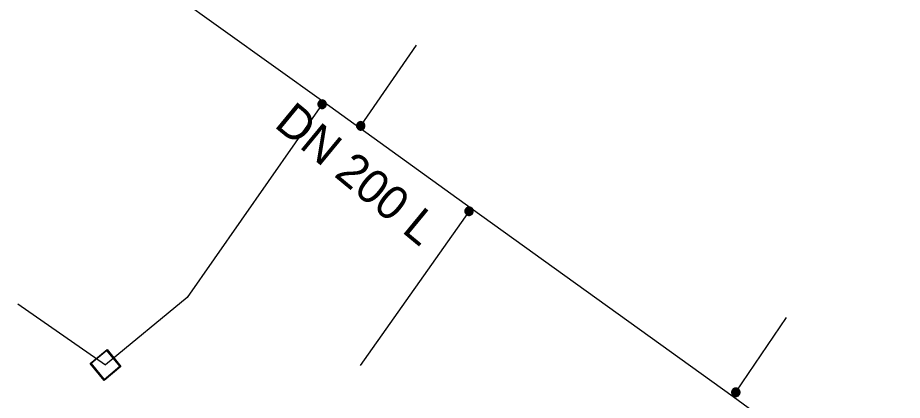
# Model space of a CAD drawing. Extents: x -832382 to -831581, y -1074670 to -1074251.
# Drawn here: x -831679.3 to -831626.9, y -1074502.9 to -1074480.2 of the extents above; entities that cross this region are included whole.
import ezdxf

# ---------------------------------------------------------------- set-up
doc = ezdxf.new("R2010")
doc.units = 0
for name, color, linetype in [('Přípojka vodovodu', 7, 'Continuous'), ('Přípojkový uzávěr', 7, 'Continuous'), ('Roz-řad', 7, 'Continuous'), ('Roz-řad-popis základní', 7, 'Continuous'), ('Šachta vodovodní', 7, 'Continuous')]:
    doc.layers.add(name, color=color, linetype=linetype)

msp = doc.modelspace()

# ---------------------------------------------------------------- linework, layer by layer
at = {"layer": 'Přípojka vodovodu'}
msp.add_line((-831679.298, -1074497.2), (-831674.092, -1074500.816), dxfattribs=at)
for points in [[(-831659.022, -1074486.757), (-831658.96, -1074486.64), (-831655.662, -1074481.85)], [(-831661.155, -1074485.222), (-831661.249, -1074485.356), (-831669.245, -1074496.822), (-831674.092, -1074500.816)], [(-831652.411, -1074491.516), (-831652.538, -1074491.697), (-831658.987, -1074500.857)], [(-831636.886, -1074502.691), (-831636.72, -1074502.44), (-831633.711, -1074498.013)]]:
    msp.add_lwpolyline(points, dxfattribs=at)
at = {"layer": 'Přípojkový uzávěr'}
for points in [[(-831661.249, -1074485.106), (-831661.186, -1074485.106), (-831661.126, -1074485.138), (-831661.066, -1074485.171), (-831661.032, -1074485.231), (-831660.999, -1074485.291), (-831660.999, -1074485.356), (-831660.999, -1074485.421), (-831661.032, -1074485.481), (-831661.065, -1074485.54), (-831661.124, -1074485.573), (-831661.184, -1074485.606), (-831661.249, -1074485.606), (-831661.314, -1074485.606), (-831661.373, -1074485.573), (-831661.433, -1074485.54), (-831661.466, -1074485.481), (-831661.499, -1074485.421), (-831661.499, -1074485.356), (-831661.499, -1074485.291), (-831661.465, -1074485.231), (-831661.432, -1074485.171), (-831661.372, -1074485.138), (-831661.312, -1074485.106), (-831661.249, -1074485.106)], [(-831661.249, -1074485.129), (-831661.306, -1074485.129), (-831661.36, -1074485.159), (-831661.414, -1074485.188), (-831661.445, -1074485.242), (-831661.475, -1074485.297), (-831661.475, -1074485.356), (-831661.475, -1074485.415), (-831661.445, -1074485.469), (-831661.416, -1074485.523), (-831661.362, -1074485.553), (-831661.307, -1074485.583), (-831661.249, -1074485.583), (-831661.19, -1074485.583), (-831661.136, -1074485.553), (-831661.082, -1074485.523), (-831661.052, -1074485.469), (-831661.022, -1074485.415), (-831661.022, -1074485.356), (-831661.022, -1074485.297), (-831661.053, -1074485.242), (-831661.084, -1074485.188), (-831661.138, -1074485.159), (-831661.192, -1074485.129), (-831661.249, -1074485.129)], [(-831661.249, -1074485.147), (-831661.196, -1074485.147), (-831661.146, -1074485.174), (-831661.096, -1074485.201), (-831661.068, -1074485.251), (-831661.039, -1074485.301), (-831661.039, -1074485.356), (-831661.039, -1074485.411), (-831661.067, -1074485.461), (-831661.094, -1074485.51), (-831661.144, -1074485.538), (-831661.194, -1074485.566), (-831661.249, -1074485.566), (-831661.303, -1074485.566), (-831661.353, -1074485.538), (-831661.403, -1074485.51), (-831661.431, -1074485.461), (-831661.458, -1074485.411), (-831661.458, -1074485.356), (-831661.458, -1074485.301), (-831661.43, -1074485.251), (-831661.402, -1074485.201), (-831661.352, -1074485.174), (-831661.302, -1074485.147), (-831661.249, -1074485.147)], [(-831661.249, -1074485.169), (-831661.327, -1074485.169), (-831661.382, -1074485.223), (-831661.436, -1074485.278), (-831661.436, -1074485.356), (-831661.436, -1074485.434), (-831661.381, -1074485.489), (-831661.326, -1074485.544), (-831661.249, -1074485.544), (-831661.171, -1074485.544), (-831661.116, -1074485.489), (-831661.061, -1074485.434), (-831661.061, -1074485.356), (-831661.061, -1074485.278), (-831661.116, -1074485.223), (-831661.17, -1074485.169), (-831661.249, -1074485.169)], [(-831661.249, -1074485.191), (-831661.181, -1074485.191), (-831661.133, -1074485.239), (-831661.085, -1074485.287), (-831661.085, -1074485.356), (-831661.085, -1074485.424), (-831661.133, -1074485.472), (-831661.181, -1074485.52), (-831661.249, -1074485.52), (-831661.317, -1074485.52), (-831661.365, -1074485.472), (-831661.413, -1074485.424), (-831661.413, -1074485.356), (-831661.413, -1074485.287), (-831661.365, -1074485.239), (-831661.317, -1074485.191), (-831661.249, -1074485.191)], [(-831661.249, -1074485.211), (-831661.309, -1074485.211), (-831661.351, -1074485.254), (-831661.393, -1074485.296), (-831661.393, -1074485.356), (-831661.393, -1074485.415), (-831661.351, -1074485.458), (-831661.309, -1074485.5), (-831661.249, -1074485.5), (-831661.189, -1074485.5), (-831661.147, -1074485.458), (-831661.105, -1074485.415), (-831661.105, -1074485.356), (-831661.105, -1074485.296), (-831661.147, -1074485.254), (-831661.189, -1074485.211), (-831661.249, -1074485.211)], [(-831661.249, -1074485.231), (-831661.196, -1074485.231), (-831661.16, -1074485.268), (-831661.124, -1074485.304), (-831661.124, -1074485.356), (-831661.124, -1074485.408), (-831661.16, -1074485.445), (-831661.197, -1074485.481), (-831661.249, -1074485.481), (-831661.3, -1074485.481), (-831661.337, -1074485.445), (-831661.374, -1074485.408), (-831661.374, -1074485.356), (-831661.374, -1074485.304), (-831661.337, -1074485.268), (-831661.301, -1074485.231), (-831661.249, -1074485.231)], [(-831661.249, -1074485.254), (-831661.291, -1074485.254), (-831661.321, -1074485.284), (-831661.35, -1074485.314), (-831661.35, -1074485.356), (-831661.35, -1074485.398), (-831661.321, -1074485.428), (-831661.291, -1074485.457), (-831661.249, -1074485.457), (-831661.207, -1074485.457), (-831661.177, -1074485.428), (-831661.147, -1074485.398), (-831661.147, -1074485.356), (-831661.147, -1074485.314), (-831661.177, -1074485.284), (-831661.207, -1074485.254), (-831661.249, -1074485.254)], [(-831661.249, -1074485.272), (-831661.214, -1074485.272), (-831661.189, -1074485.296), (-831661.165, -1074485.321), (-831661.165, -1074485.356), (-831661.165, -1074485.391), (-831661.189, -1074485.415), (-831661.214, -1074485.44), (-831661.249, -1074485.44), (-831661.284, -1074485.44), (-831661.309, -1074485.415), (-831661.333, -1074485.391), (-831661.333, -1074485.356), (-831661.333, -1074485.321), (-831661.309, -1074485.296), (-831661.284, -1074485.272), (-831661.249, -1074485.272)], [(-831661.249, -1074485.294), (-831661.275, -1074485.294), (-831661.293, -1074485.312), (-831661.311, -1074485.33), (-831661.311, -1074485.356), (-831661.311, -1074485.382), (-831661.293, -1074485.4), (-831661.275, -1074485.419), (-831661.249, -1074485.419), (-831661.223, -1074485.419), (-831661.204, -1074485.4), (-831661.186, -1074485.382), (-831661.186, -1074485.356), (-831661.186, -1074485.33), (-831661.204, -1074485.312), (-831661.223, -1074485.294), (-831661.249, -1074485.294)], [(-831661.249, -1074485.317), (-831661.232, -1074485.317), (-831661.221, -1074485.328), (-831661.21, -1074485.339), (-831661.21, -1074485.356), (-831661.21, -1074485.372), (-831661.221, -1074485.384), (-831661.232, -1074485.395), (-831661.249, -1074485.395), (-831661.265, -1074485.395), (-831661.276, -1074485.384), (-831661.288, -1074485.372), (-831661.288, -1074485.356), (-831661.288, -1074485.339), (-831661.276, -1074485.328), (-831661.265, -1074485.317), (-831661.249, -1074485.317)], [(-831661.249, -1074485.333), (-831661.259, -1074485.333), (-831661.265, -1074485.339), (-831661.272, -1074485.346), (-831661.272, -1074485.356), (-831661.272, -1074485.366), (-831661.265, -1074485.373), (-831661.259, -1074485.379), (-831661.249, -1074485.379), (-831661.239, -1074485.379), (-831661.232, -1074485.373), (-831661.225, -1074485.366), (-831661.225, -1074485.356), (-831661.225, -1074485.346), (-831661.232, -1074485.339), (-831661.239, -1074485.333), (-831661.249, -1074485.333)], [(-831658.96, -1074486.39), (-831658.897, -1074486.39), (-831658.837, -1074486.422), (-831658.778, -1074486.454), (-831658.744, -1074486.515), (-831658.71, -1074486.575), (-831658.71, -1074486.64), (-831658.71, -1074486.705), (-831658.743, -1074486.765), (-831658.776, -1074486.824), (-831658.835, -1074486.857), (-831658.895, -1074486.89), (-831658.96, -1074486.89), (-831659.025, -1074486.89), (-831659.085, -1074486.857), (-831659.144, -1074486.824), (-831659.177, -1074486.765), (-831659.21, -1074486.705), (-831659.21, -1074486.64), (-831659.21, -1074486.575), (-831659.176, -1074486.515), (-831659.143, -1074486.454), (-831659.083, -1074486.422), (-831659.023, -1074486.39), (-831658.96, -1074486.39)], [(-831658.96, -1074486.413), (-831659.017, -1074486.413), (-831659.072, -1074486.443), (-831659.126, -1074486.472), (-831659.156, -1074486.526), (-831659.187, -1074486.581), (-831659.187, -1074486.64), (-831659.187, -1074486.699), (-831659.157, -1074486.753), (-831659.127, -1074486.807), (-831659.073, -1074486.837), (-831659.019, -1074486.867), (-831658.96, -1074486.867), (-831658.901, -1074486.867), (-831658.847, -1074486.837), (-831658.793, -1074486.807), (-831658.763, -1074486.753), (-831658.733, -1074486.699), (-831658.733, -1074486.64), (-831658.733, -1074486.581), (-831658.764, -1074486.526), (-831658.795, -1074486.472), (-831658.849, -1074486.443), (-831658.903, -1074486.413), (-831658.96, -1074486.413)], [(-831658.96, -1074486.431), (-831658.907, -1074486.431), (-831658.857, -1074486.458), (-831658.807, -1074486.484), (-831658.779, -1074486.535), (-831658.751, -1074486.585), (-831658.751, -1074486.64), (-831658.751, -1074486.695), (-831658.778, -1074486.744), (-831658.805, -1074486.794), (-831658.856, -1074486.822), (-831658.906, -1074486.849), (-831658.96, -1074486.849), (-831659.014, -1074486.849), (-831659.064, -1074486.822), (-831659.115, -1074486.794), (-831659.142, -1074486.744), (-831659.169, -1074486.695), (-831659.169, -1074486.64), (-831659.169, -1074486.585), (-831659.141, -1074486.535), (-831659.113, -1074486.484), (-831659.063, -1074486.458), (-831659.013, -1074486.431), (-831658.96, -1074486.431)], [(-831658.96, -1074486.453), (-831659.039, -1074486.453), (-831659.093, -1074486.507), (-831659.147, -1074486.562), (-831659.147, -1074486.64), (-831659.147, -1074486.718), (-831659.093, -1074486.773), (-831659.038, -1074486.828), (-831658.96, -1074486.828), (-831658.882, -1074486.828), (-831658.827, -1074486.773), (-831658.772, -1074486.718), (-831658.772, -1074486.64), (-831658.772, -1074486.562), (-831658.827, -1074486.507), (-831658.882, -1074486.453), (-831658.96, -1074486.453)], [(-831658.96, -1074486.475), (-831658.892, -1074486.475), (-831658.844, -1074486.523), (-831658.796, -1074486.571), (-831658.796, -1074486.64), (-831658.796, -1074486.708), (-831658.844, -1074486.756), (-831658.892, -1074486.804), (-831658.96, -1074486.804), (-831659.029, -1074486.804), (-831659.077, -1074486.756), (-831659.125, -1074486.708), (-831659.125, -1074486.64), (-831659.125, -1074486.571), (-831659.077, -1074486.523), (-831659.029, -1074486.475), (-831658.96, -1074486.475)], [(-831658.96, -1074486.495), (-831659.021, -1074486.495), (-831659.063, -1074486.537), (-831659.105, -1074486.58), (-831659.105, -1074486.64), (-831659.105, -1074486.699), (-831659.063, -1074486.742), (-831659.021, -1074486.784), (-831658.96, -1074486.784), (-831658.901, -1074486.784), (-831658.858, -1074486.742), (-831658.816, -1074486.699), (-831658.816, -1074486.64), (-831658.816, -1074486.58), (-831658.858, -1074486.537), (-831658.9, -1074486.495), (-831658.96, -1074486.495)], [(-831658.96, -1074486.515), (-831658.908, -1074486.515), (-831658.871, -1074486.552), (-831658.835, -1074486.588), (-831658.835, -1074486.64), (-831658.835, -1074486.692), (-831658.872, -1074486.729), (-831658.908, -1074486.765), (-831658.96, -1074486.765), (-831659.012, -1074486.765), (-831659.048, -1074486.729), (-831659.085, -1074486.692), (-831659.085, -1074486.64), (-831659.085, -1074486.588), (-831659.049, -1074486.552), (-831659.012, -1074486.515), (-831658.96, -1074486.515)], [(-831658.96, -1074486.538), (-831659.002, -1074486.538), (-831659.032, -1074486.568), (-831659.062, -1074486.598), (-831659.062, -1074486.64), (-831659.062, -1074486.682), (-831659.032, -1074486.712), (-831659.002, -1074486.741), (-831658.96, -1074486.741), (-831658.918, -1074486.741), (-831658.888, -1074486.712), (-831658.859, -1074486.682), (-831658.859, -1074486.64), (-831658.859, -1074486.598), (-831658.888, -1074486.568), (-831658.918, -1074486.538), (-831658.96, -1074486.538)], [(-831658.96, -1074486.556), (-831658.925, -1074486.556), (-831658.901, -1074486.58), (-831658.876, -1074486.605), (-831658.876, -1074486.64), (-831658.876, -1074486.675), (-831658.901, -1074486.699), (-831658.925, -1074486.724), (-831658.96, -1074486.724), (-831658.995, -1074486.724), (-831659.02, -1074486.699), (-831659.044, -1074486.675), (-831659.044, -1074486.64), (-831659.044, -1074486.605), (-831659.02, -1074486.58), (-831658.995, -1074486.556), (-831658.96, -1074486.556)], [(-831658.96, -1074486.578), (-831658.986, -1074486.578), (-831659.004, -1074486.596), (-831659.022, -1074486.614), (-831659.022, -1074486.64), (-831659.022, -1074486.666), (-831659.004, -1074486.684), (-831658.986, -1074486.703), (-831658.96, -1074486.703), (-831658.934, -1074486.703), (-831658.916, -1074486.684), (-831658.897, -1074486.666), (-831658.897, -1074486.64), (-831658.897, -1074486.614), (-831658.916, -1074486.596), (-831658.934, -1074486.578), (-831658.96, -1074486.578)], [(-831658.96, -1074486.601), (-831658.944, -1074486.601), (-831658.932, -1074486.612), (-831658.921, -1074486.623), (-831658.921, -1074486.64), (-831658.921, -1074486.656), (-831658.932, -1074486.668), (-831658.944, -1074486.679), (-831658.96, -1074486.679), (-831658.976, -1074486.679), (-831658.988, -1074486.668), (-831658.999, -1074486.656), (-831658.999, -1074486.64), (-831658.999, -1074486.623), (-831658.988, -1074486.612), (-831658.976, -1074486.601), (-831658.96, -1074486.601)], [(-831658.96, -1074486.617), (-831658.97, -1074486.617), (-831658.977, -1074486.623), (-831658.984, -1074486.63), (-831658.984, -1074486.64), (-831658.984, -1074486.65), (-831658.977, -1074486.657), (-831658.97, -1074486.663), (-831658.96, -1074486.663), (-831658.95, -1074486.663), (-831658.944, -1074486.657), (-831658.937, -1074486.65), (-831658.937, -1074486.64), (-831658.937, -1074486.63), (-831658.944, -1074486.623), (-831658.95, -1074486.617), (-831658.96, -1074486.617)], [(-831652.538, -1074491.447), (-831652.475, -1074491.447), (-831652.416, -1074491.479), (-831652.356, -1074491.511), (-831652.322, -1074491.571), (-831652.288, -1074491.632), (-831652.288, -1074491.697), (-831652.288, -1074491.762), (-831652.321, -1074491.821), (-831652.354, -1074491.881), (-831652.414, -1074491.914), (-831652.473, -1074491.947), (-831652.538, -1074491.947), (-831652.603, -1074491.947), (-831652.663, -1074491.914), (-831652.722, -1074491.881), (-831652.755, -1074491.821), (-831652.788, -1074491.762), (-831652.788, -1074491.697), (-831652.788, -1074491.632), (-831652.755, -1074491.571), (-831652.721, -1074491.511), (-831652.661, -1074491.479), (-831652.602, -1074491.447), (-831652.538, -1074491.447)], [(-831652.538, -1074491.47), (-831652.596, -1074491.47), (-831652.65, -1074491.499), (-831652.704, -1074491.529), (-831652.734, -1074491.583), (-831652.765, -1074491.638), (-831652.765, -1074491.697), (-831652.765, -1074491.756), (-831652.735, -1074491.81), (-831652.705, -1074491.864), (-831652.651, -1074491.893), (-831652.597, -1074491.923), (-831652.538, -1074491.923), (-831652.479, -1074491.923), (-831652.425, -1074491.893), (-831652.371, -1074491.864), (-831652.341, -1074491.81), (-831652.312, -1074491.756), (-831652.312, -1074491.697), (-831652.312, -1074491.638), (-831652.342, -1074491.583), (-831652.373, -1074491.529), (-831652.427, -1074491.499), (-831652.481, -1074491.47), (-831652.538, -1074491.47)], [(-831652.538, -1074491.487), (-831652.485, -1074491.487), (-831652.436, -1074491.514), (-831652.386, -1074491.541), (-831652.357, -1074491.592), (-831652.329, -1074491.642), (-831652.329, -1074491.697), (-831652.329, -1074491.751), (-831652.356, -1074491.801), (-831652.384, -1074491.851), (-831652.434, -1074491.879), (-831652.484, -1074491.906), (-831652.538, -1074491.906), (-831652.593, -1074491.906), (-831652.643, -1074491.879), (-831652.693, -1074491.851), (-831652.72, -1074491.801), (-831652.748, -1074491.751), (-831652.748, -1074491.697), (-831652.748, -1074491.642), (-831652.72, -1074491.592), (-831652.692, -1074491.541), (-831652.641, -1074491.514), (-831652.591, -1074491.487), (-831652.538, -1074491.487)], [(-831652.539, -1074491.509), (-831652.617, -1074491.509), (-831652.671, -1074491.564), (-831652.726, -1074491.619), (-831652.726, -1074491.697), (-831652.726, -1074491.775), (-831652.671, -1074491.829), (-831652.616, -1074491.884), (-831652.539, -1074491.884), (-831652.461, -1074491.884), (-831652.406, -1074491.829), (-831652.351, -1074491.775), (-831652.351, -1074491.697), (-831652.351, -1074491.619), (-831652.405, -1074491.564), (-831652.46, -1074491.509), (-831652.539, -1074491.509)], [(-831652.539, -1074491.532), (-831652.47, -1074491.532), (-831652.422, -1074491.58), (-831652.375, -1074491.628), (-831652.375, -1074491.696), (-831652.375, -1074491.764), (-831652.423, -1074491.812), (-831652.471, -1074491.86), (-831652.539, -1074491.86), (-831652.607, -1074491.86), (-831652.655, -1074491.812), (-831652.703, -1074491.764), (-831652.703, -1074491.696), (-831652.703, -1074491.628), (-831652.655, -1074491.58), (-831652.607, -1074491.532), (-831652.539, -1074491.532)], [(-831652.539, -1074491.552), (-831652.599, -1074491.552), (-831652.641, -1074491.594), (-831652.683, -1074491.637), (-831652.683, -1074491.696), (-831652.683, -1074491.756), (-831652.641, -1074491.798), (-831652.599, -1074491.841), (-831652.539, -1074491.841), (-831652.479, -1074491.841), (-831652.437, -1074491.798), (-831652.394, -1074491.756), (-831652.394, -1074491.696), (-831652.394, -1074491.637), (-831652.436, -1074491.594), (-831652.478, -1074491.552), (-831652.539, -1074491.552)], [(-831652.538, -1074491.572), (-831652.486, -1074491.572), (-831652.45, -1074491.608), (-831652.413, -1074491.645), (-831652.413, -1074491.697), (-831652.413, -1074491.749), (-831652.45, -1074491.785), (-831652.486, -1074491.822), (-831652.538, -1074491.822), (-831652.59, -1074491.822), (-831652.627, -1074491.785), (-831652.663, -1074491.749), (-831652.663, -1074491.697), (-831652.663, -1074491.645), (-831652.627, -1074491.608), (-831652.591, -1074491.572), (-831652.538, -1074491.572)], [(-831652.538, -1074491.595), (-831652.581, -1074491.595), (-831652.61, -1074491.625), (-831652.64, -1074491.654), (-831652.64, -1074491.697), (-831652.64, -1074491.739), (-831652.61, -1074491.768), (-831652.581, -1074491.798), (-831652.538, -1074491.798), (-831652.496, -1074491.798), (-831652.467, -1074491.768), (-831652.437, -1074491.739), (-831652.437, -1074491.697), (-831652.437, -1074491.654), (-831652.467, -1074491.625), (-831652.496, -1074491.595), (-831652.538, -1074491.595)], [(-831652.538, -1074491.612), (-831652.503, -1074491.612), (-831652.479, -1074491.637), (-831652.454, -1074491.661), (-831652.454, -1074491.697), (-831652.454, -1074491.732), (-831652.479, -1074491.756), (-831652.504, -1074491.781), (-831652.538, -1074491.781), (-831652.574, -1074491.781), (-831652.598, -1074491.756), (-831652.623, -1074491.732), (-831652.623, -1074491.697), (-831652.623, -1074491.661), (-831652.598, -1074491.637), (-831652.574, -1074491.612), (-831652.538, -1074491.612)], [(-831652.538, -1074491.634), (-831652.564, -1074491.634), (-831652.583, -1074491.653), (-831652.601, -1074491.671), (-831652.601, -1074491.697), (-831652.601, -1074491.723), (-831652.582, -1074491.741), (-831652.564, -1074491.759), (-831652.538, -1074491.759), (-831652.512, -1074491.759), (-831652.494, -1074491.741), (-831652.476, -1074491.723), (-831652.476, -1074491.697), (-831652.476, -1074491.671), (-831652.494, -1074491.653), (-831652.512, -1074491.634), (-831652.538, -1074491.634)], [(-831652.538, -1074491.658), (-831652.522, -1074491.658), (-831652.511, -1074491.669), (-831652.499, -1074491.68), (-831652.499, -1074491.697), (-831652.499, -1074491.713), (-831652.511, -1074491.724), (-831652.522, -1074491.736), (-831652.538, -1074491.736), (-831652.555, -1074491.736), (-831652.566, -1074491.724), (-831652.578, -1074491.713), (-831652.578, -1074491.697), (-831652.578, -1074491.68), (-831652.566, -1074491.669), (-831652.555, -1074491.658), (-831652.538, -1074491.658)], [(-831652.538, -1074491.673), (-831652.548, -1074491.673), (-831652.555, -1074491.68), (-831652.562, -1074491.687), (-831652.562, -1074491.697), (-831652.562, -1074491.707), (-831652.555, -1074491.713), (-831652.548, -1074491.72), (-831652.538, -1074491.72), (-831652.528, -1074491.72), (-831652.522, -1074491.713), (-831652.515, -1074491.707), (-831652.515, -1074491.697), (-831652.515, -1074491.687), (-831652.522, -1074491.68), (-831652.528, -1074491.673), (-831652.538, -1074491.673)], [(-831636.72, -1074502.19), (-831636.657, -1074502.19), (-831636.597, -1074502.222), (-831636.538, -1074502.254), (-831636.504, -1074502.315), (-831636.47, -1074502.375), (-831636.47, -1074502.44), (-831636.47, -1074502.505), (-831636.503, -1074502.565), (-831636.536, -1074502.624), (-831636.595, -1074502.657), (-831636.655, -1074502.69), (-831636.72, -1074502.69), (-831636.785, -1074502.69), (-831636.845, -1074502.657), (-831636.904, -1074502.624), (-831636.937, -1074502.565), (-831636.97, -1074502.505), (-831636.97, -1074502.44), (-831636.97, -1074502.375), (-831636.936, -1074502.315), (-831636.903, -1074502.254), (-831636.843, -1074502.222), (-831636.783, -1074502.19), (-831636.72, -1074502.19)], [(-831636.72, -1074502.213), (-831636.777, -1074502.213), (-831636.832, -1074502.243), (-831636.886, -1074502.272), (-831636.916, -1074502.326), (-831636.947, -1074502.381), (-831636.947, -1074502.44), (-831636.947, -1074502.499), (-831636.917, -1074502.553), (-831636.887, -1074502.607), (-831636.833, -1074502.637), (-831636.779, -1074502.667), (-831636.72, -1074502.667), (-831636.661, -1074502.667), (-831636.607, -1074502.637), (-831636.553, -1074502.607), (-831636.523, -1074502.553), (-831636.493, -1074502.499), (-831636.493, -1074502.44), (-831636.493, -1074502.381), (-831636.524, -1074502.326), (-831636.555, -1074502.272), (-831636.609, -1074502.243), (-831636.663, -1074502.213), (-831636.72, -1074502.213)], [(-831636.72, -1074502.231), (-831636.667, -1074502.231), (-831636.617, -1074502.258), (-831636.567, -1074502.284), (-831636.539, -1074502.335), (-831636.511, -1074502.385), (-831636.511, -1074502.44), (-831636.511, -1074502.495), (-831636.538, -1074502.544), (-831636.565, -1074502.594), (-831636.616, -1074502.622), (-831636.666, -1074502.649), (-831636.72, -1074502.649), (-831636.774, -1074502.649), (-831636.824, -1074502.622), (-831636.875, -1074502.594), (-831636.902, -1074502.544), (-831636.929, -1074502.495), (-831636.929, -1074502.44), (-831636.929, -1074502.385), (-831636.901, -1074502.335), (-831636.873, -1074502.284), (-831636.823, -1074502.258), (-831636.773, -1074502.231), (-831636.72, -1074502.231)], [(-831636.72, -1074502.252), (-831636.799, -1074502.252), (-831636.853, -1074502.307), (-831636.907, -1074502.362), (-831636.907, -1074502.44), (-831636.907, -1074502.518), (-831636.853, -1074502.573), (-831636.798, -1074502.627), (-831636.72, -1074502.627), (-831636.642, -1074502.627), (-831636.587, -1074502.573), (-831636.532, -1074502.518), (-831636.532, -1074502.44), (-831636.532, -1074502.362), (-831636.587, -1074502.307), (-831636.642, -1074502.252), (-831636.72, -1074502.252)], [(-831636.72, -1074502.275), (-831636.652, -1074502.275), (-831636.604, -1074502.323), (-831636.556, -1074502.371), (-831636.556, -1074502.44), (-831636.556, -1074502.508), (-831636.604, -1074502.556), (-831636.652, -1074502.604), (-831636.72, -1074502.604), (-831636.789, -1074502.604), (-831636.837, -1074502.556), (-831636.885, -1074502.508), (-831636.885, -1074502.44), (-831636.885, -1074502.371), (-831636.837, -1074502.323), (-831636.789, -1074502.275), (-831636.72, -1074502.275)], [(-831636.72, -1074502.295), (-831636.781, -1074502.295), (-831636.823, -1074502.337), (-831636.865, -1074502.38), (-831636.865, -1074502.44), (-831636.865, -1074502.499), (-831636.823, -1074502.542), (-831636.781, -1074502.584), (-831636.72, -1074502.584), (-831636.661, -1074502.584), (-831636.618, -1074502.542), (-831636.576, -1074502.499), (-831636.576, -1074502.44), (-831636.576, -1074502.38), (-831636.618, -1074502.337), (-831636.66, -1074502.295), (-831636.72, -1074502.295)], [(-831636.72, -1074502.315), (-831636.668, -1074502.315), (-831636.631, -1074502.352), (-831636.595, -1074502.388), (-831636.595, -1074502.44), (-831636.595, -1074502.492), (-831636.632, -1074502.529), (-831636.668, -1074502.565), (-831636.72, -1074502.565), (-831636.772, -1074502.565), (-831636.808, -1074502.529), (-831636.845, -1074502.492), (-831636.845, -1074502.44), (-831636.845, -1074502.388), (-831636.809, -1074502.352), (-831636.772, -1074502.315), (-831636.72, -1074502.315)], [(-831636.72, -1074502.338), (-831636.762, -1074502.338), (-831636.792, -1074502.368), (-831636.822, -1074502.398), (-831636.822, -1074502.44), (-831636.822, -1074502.482), (-831636.792, -1074502.512), (-831636.762, -1074502.541), (-831636.72, -1074502.541), (-831636.678, -1074502.541), (-831636.648, -1074502.512), (-831636.619, -1074502.482), (-831636.619, -1074502.44), (-831636.619, -1074502.398), (-831636.648, -1074502.368), (-831636.678, -1074502.338), (-831636.72, -1074502.338)], [(-831636.72, -1074502.356), (-831636.685, -1074502.356), (-831636.661, -1074502.38), (-831636.636, -1074502.405), (-831636.636, -1074502.44), (-831636.636, -1074502.475), (-831636.661, -1074502.499), (-831636.685, -1074502.524), (-831636.72, -1074502.524), (-831636.755, -1074502.524), (-831636.78, -1074502.499), (-831636.804, -1074502.475), (-831636.804, -1074502.44), (-831636.804, -1074502.405), (-831636.78, -1074502.38), (-831636.755, -1074502.356), (-831636.72, -1074502.356)], [(-831636.72, -1074502.377), (-831636.746, -1074502.377), (-831636.764, -1074502.396), (-831636.782, -1074502.414), (-831636.782, -1074502.44), (-831636.782, -1074502.466), (-831636.764, -1074502.484), (-831636.746, -1074502.502), (-831636.72, -1074502.502), (-831636.694, -1074502.502), (-831636.676, -1074502.484), (-831636.657, -1074502.466), (-831636.657, -1074502.44), (-831636.657, -1074502.414), (-831636.676, -1074502.396), (-831636.694, -1074502.377), (-831636.72, -1074502.377)], [(-831636.72, -1074502.401), (-831636.704, -1074502.401), (-831636.692, -1074502.412), (-831636.681, -1074502.423), (-831636.681, -1074502.44), (-831636.681, -1074502.456), (-831636.692, -1074502.468), (-831636.704, -1074502.479), (-831636.72, -1074502.479), (-831636.736, -1074502.479), (-831636.748, -1074502.468), (-831636.759, -1074502.456), (-831636.759, -1074502.44), (-831636.759, -1074502.423), (-831636.748, -1074502.412), (-831636.736, -1074502.401), (-831636.72, -1074502.401)], [(-831636.72, -1074502.417), (-831636.73, -1074502.417), (-831636.737, -1074502.423), (-831636.744, -1074502.43), (-831636.744, -1074502.44), (-831636.744, -1074502.45), (-831636.737, -1074502.457), (-831636.73, -1074502.463), (-831636.72, -1074502.463), (-831636.71, -1074502.463), (-831636.704, -1074502.457), (-831636.697, -1074502.45), (-831636.697, -1074502.44), (-831636.697, -1074502.43), (-831636.704, -1074502.423), (-831636.71, -1074502.417), (-831636.72, -1074502.417)]]:
    msp.add_open_spline(points, degree=3, dxfattribs=at)
at = {"layer": 'Roz-řad'}
msp.add_lwpolyline([(-831670.1, -1074478.783), (-831661.155, -1074485.222), (-831659.022, -1074486.757), (-831652.411, -1074491.516), (-831636.886, -1074502.691), (-831632.509, -1074505.888), (-831582.314, -1074542.549), (-831580.799, -1074543.602), (-831583.872, -1074547.6)], dxfattribs=at)
at = {"layer": 'Šachta vodovodní'}
for points in [[(-831674.003, -1074499.901), (-831673.177, -1074500.904), (-831674.18, -1074501.731), (-831675.007, -1074500.728), (-831674.003, -1074499.901)], [(-831674.949, -1074500.733), (-831674.174, -1074501.674), (-831673.234, -1074500.899), (-831674.009, -1074499.958), (-831674.949, -1074500.733)]]:
    msp.add_lwpolyline(points, dxfattribs=at)

# ---------------------------------------------------------------- texts
at = {"layer": 'Roz-řad-popis základní'}
msp.add_text('DN 200 L', height=2, rotation=320.4805, dxfattribs=at).set_placement((-831664.154, -1074486.657))

doc.saveas('drawing.dxf')
